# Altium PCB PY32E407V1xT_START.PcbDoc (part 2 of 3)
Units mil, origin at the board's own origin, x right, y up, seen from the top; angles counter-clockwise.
Board outline 1968.43 x 4717 mil, 2 copper layers (Top Layer, Bottom Layer), stack 21 mil thick; 210 components, 217 nets, 824 pads, 371 vias.
Unrouted connection lines stored in the file: 1.
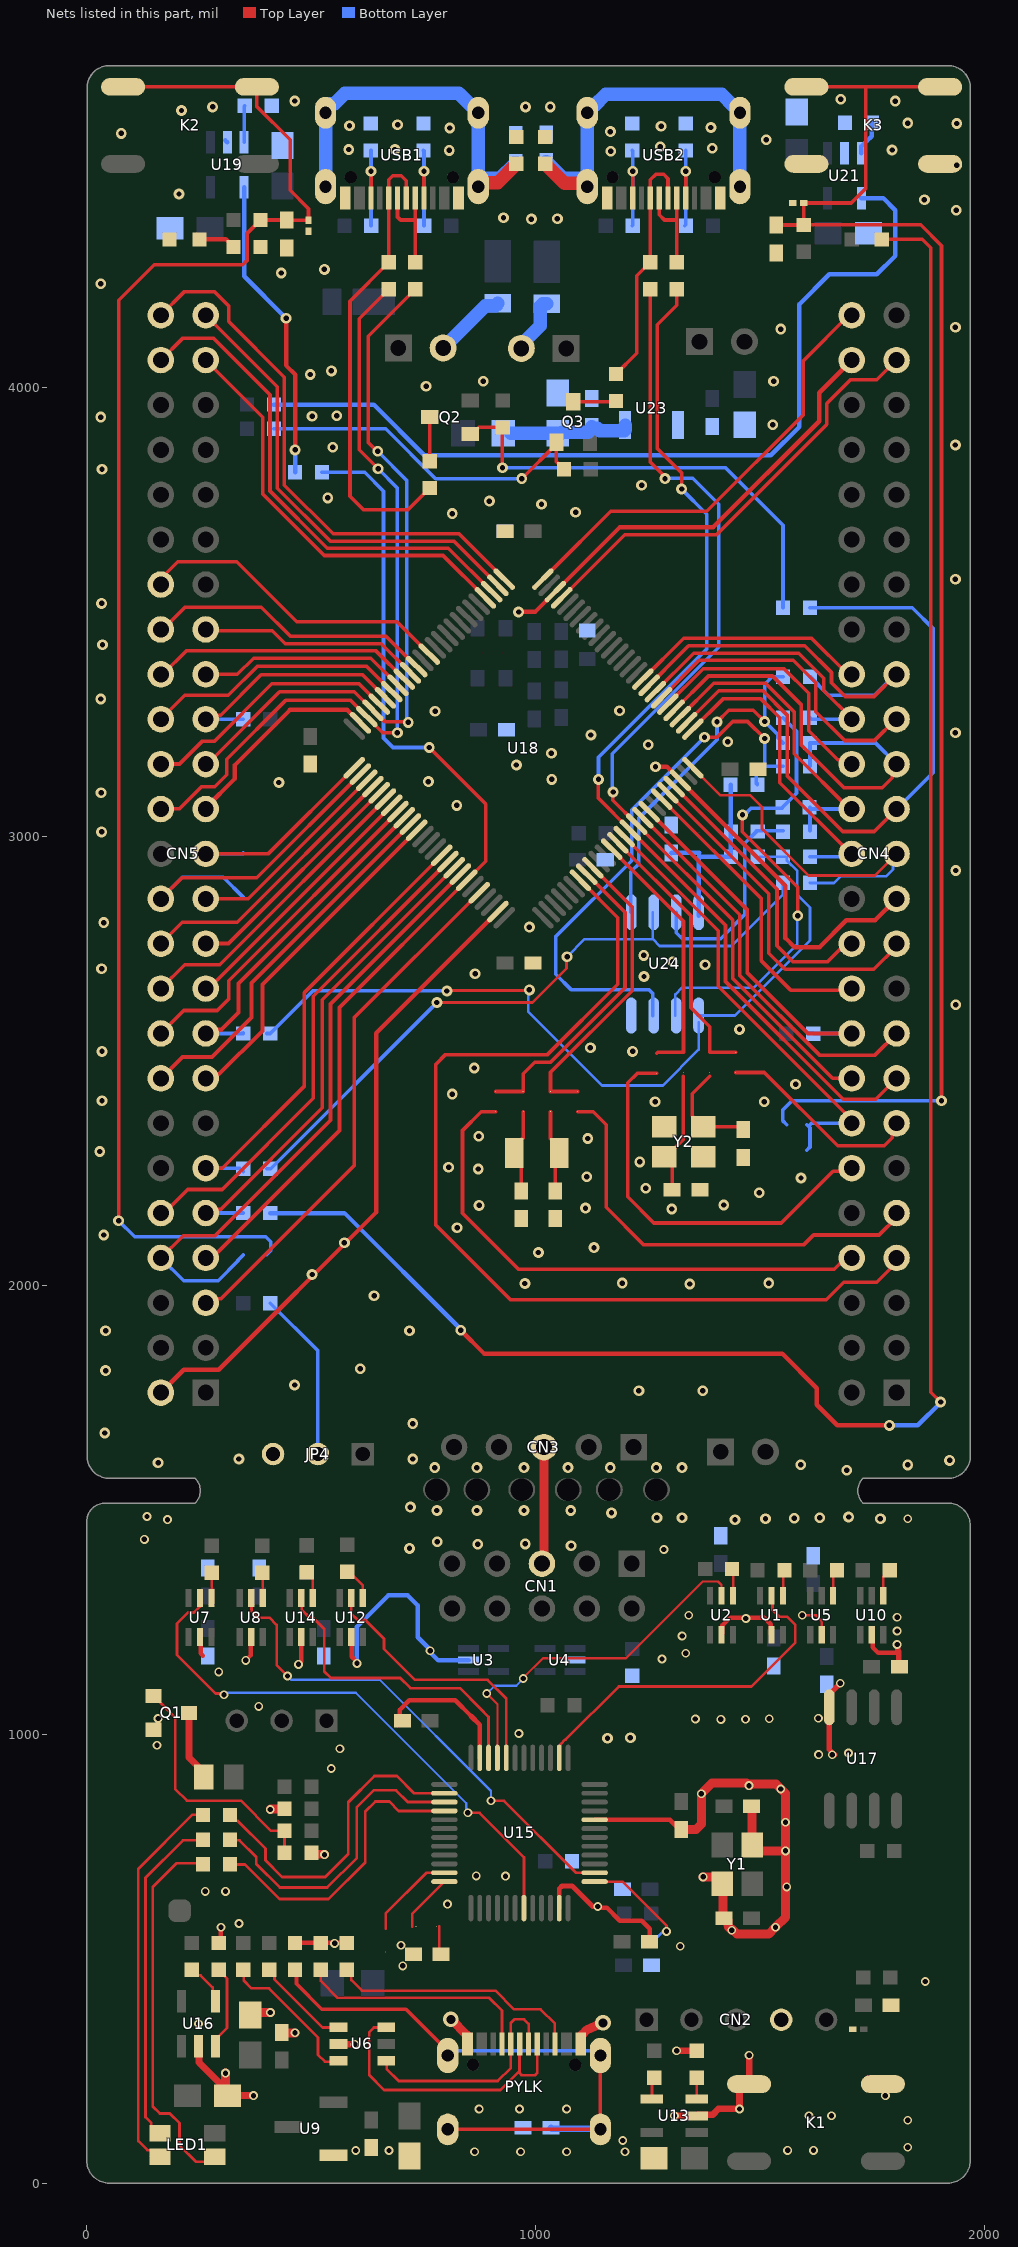
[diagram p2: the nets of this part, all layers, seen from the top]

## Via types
v1: diameter 24, hole 12, Top Layer to Bottom Layer, tented both sides, 208 vias
v2: diameter 19.68, hole 11.81, Top Layer to Bottom Layer, tented both sides, 106 vias
v3: diameter 19.68, hole 11.81, Top Layer to Bottom Layer, 37 vias
v4: diameter 35, hole 20, Top Layer to Bottom Layer, tented both sides, 16 vias
v5: diameter 30, hole 15, Top Layer to Bottom Layer, tented both sides, 2 vias
v6: diameter 40, hole 20, Top Layer to Bottom Layer, tented both sides, 2 vias

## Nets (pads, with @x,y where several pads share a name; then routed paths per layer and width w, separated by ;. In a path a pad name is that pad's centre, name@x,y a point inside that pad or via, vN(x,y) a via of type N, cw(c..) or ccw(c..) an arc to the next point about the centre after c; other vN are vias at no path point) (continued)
DIR_TCK_SWCLK: U2.5 U15.21 | length 808
  Top Layer w5: v2(891.12,1090.67) 914.79,1067 U15.21@914.79,947.32 ; v3(972.49,1124.13) 972.49,1125.57 1016.33,1169.41 1201.34,1169.41 1315.71,1283.79 1372.38,1340.46 1406.19,1340.46 1414.21,1332.43 U2.5@1414.21,1308.31
  Bottom Layer w5: v2(891.12,1090.67) 908.61,1108.16 956.52,1108.16 v3(972.49,1124.13)
DIR_TDI_VCP_TX: U12.5 U15.20 | length 603.7
  Top Layer w6: U12.5@589.12,1303.31 589.12,1268.77 602.92,1254.98 619.97,1254.98 662.25,1212.7 662.25,1189.92 731.11,1121.06 892.64,1121.06 934.47,1079.24 U15.20@934.47,947.32
DIR_TDO_SWO: U7.5 U15.43 | length 1242.4
  Top Layer w6: U7.5@252.55,1303.31 252.55,1284.73 238.94,1271.13 225.97,1271.13 201.14,1246.3 201.14,1176.38 286.99,1090.52 302.93,1090.52 v3(305.55,1087.9) ; v2(849,825) 874.69,825 973.84,725.85 U15.43@973.84,612.68
  Bottom Layer w5: v3(305.55,1087.9) 310.05,1092.41 599.21,1092.41 845.36,846.25 845.36,828.64 v2(849,825)
DIR_TMS_SWDIO: U1.5 U15.14 | length 784.3
  Top Layer w6: U15.14@1052.58,947.32 1052.58,973.99 1055.95,977.36 1055.95,978.29 1065.51,987.85 1066.44,987.85 1185.13,1106.54 1480.8,1106.54 1578.4,1204.13 1578.4,1243.36 1559.78,1261.98 1542.79,1261.98 1527.52,1277.25 1527.52,1306.42 U1.5@1525.64,1308.31
DIR_TRST_RTS: U8.5 U15.2 | length 1100.7
  Top Layer w6: U8.5@366.26,1303.31 366.85,1302.72 366.85,1274.24 381.53,1259.56 407.14,1259.56 422.94,1243.76 422.94,1153.79 v2(447.06,1129.67) ; v2(900.52,851.68) 929.72,851.68 1089.98,691.42 U15.2@1131.32,691.42
  Bottom Layer w5: v2(447.06,1129.67) 455.33,1121.41 652.59,1121.41 900.52,873.48 v2(900.52,851.68)
DIR_VCP_RX: U14.5 U15.22 | length 688.5
  Top Layer w6: U14.5@477.69,1303.31 479.07,1301.93 479.07,1277.14 495.6,1260.6 503.2,1260.6 529,1234.81 529,1140.06 543.61,1125.45 698.3,1125.45 721.05,1102.71 831.18,1102.71 875.38,1058.51 895.1,1038.79 U15.22@895.1,947.32
ESMC_CLK: R69.1 R70.1 U24.6 | length 1516.3
  Top Layer w6: v1(780,2630) 993.08,2630 1068.77,2705.69 1068.77,2730.51 v1(1070,2731.74)
  Bottom Layer w6: v1(1070,2731.74) 1109.26,2771 1261,2771 ; U24.6@1261,2831 1261,2771 ; R69.1@1551.01,2897 1551.01,2871.01 1436,2756 1276,2756 1261,2771
  Bottom Layer w8: R70.1@400.75,2260 410,2260 v1(780,2630)
ESMC_CS: R62.1 R67.1 R68.1 U24.1 | length 1810
  Top Layer w6: v1(802.28,2655.72) 803.42,2656.86 984.86,2656.86 v1(986,2658)
  Bottom Layer w6: v1(986,2658) 983.13,2655.13 983.13,2610.3 1148.11,2445.32 1283.32,2445.32 1363,2525 1363,2585.54 U24.1@1363,2583.32 ; U24.1@1361,2601 1443.8,2601 1611,2768.2 1611,2841.6 1583,2869.6 1583,2923.01 1559.26,2946.75 1559.26,2955 R62.1@1495,2954.99
  Bottom Layer w8: R67.1@400.75,2561 R67.1@409,2561 503.72,2655.72 v1(802.28,2655.72)
ESMC_IO0: R71.1 R74.1 U24.5 | length 826.7
  Top Layer w8: v1(1404,3255) 1430,3281 1485,3281 v1(1510,3256)
  Bottom Layer w8: U24.5@1212,2831 1212,2921.37 1230,2939.37 1230,3041.06 1404,3215.06 v1(1404,3255) ; R74.1@1551.01,3208 1539.01,3220 1539.01,3226.99 v1(1510,3256) 1510,3339 1527,3356 R71.1@1551.01,3356
ESMC_IO1: R72.1 R73.1 U24.2 | length 1023.9
  Top Layer w8: v1(1460.82,3047.82) 1460.43,3047.43 1460.43,3010.57 1584,2887 v1(1584,2823)
  Bottom Layer w6: U24.2@1311,2601 1311,2648 1326,2663 1486,2663 1583,2760 1583,2822 v1(1584,2823)
  Bottom Layer w8: v1(1460.82,3047.82) 1465.15,3047.82 1480.43,3063.1 R72.1@1549.11,3063.1 ; R72.1@1550,3065 1581,3096 1581,3234.01 R73.1@1551.01,3264
ESMC_IO2: R75.1 R76.1 U24.3 | length 1279.4
  Top Layer w8: v1(1376,3221) 1404,3221 1439,3256 1472,3256 v1(1510,3218)
  Bottom Layer w8: U24.3@1261,2601 1261,2650 1253,2658 1080,2658 1045,2693 1045,2777 1214,2946 1214,3059 v1(1376,3221) ; R76.1@1494,3118 R76.1@1494,3115 1491,3118 1491,3139 1491,3156 1510,3156 ; v1(1510,3218) 1510,3156 ; R75.1@1551.01,3156 1510,3156
ESMC_IO3: R77.1 R78.1 U24.7 | length 481.6
  Bottom Layer w8: U24.7@1313,2831 1313.47,2830.53 1313.47,2785.53 1327,2772 1412,2772 1466,2826 1466,2985 R78.1@1492,3011 ; R78.1@1491.38,3013 R77.1@1551.01,3013
F_VDD: C53.2 R50.2 R62.2 R76.2 R78.2 U24.8 | length 426.4
  Bottom Layer w10: C53.2@1302,2963 1303,2964 R50.2@1364,2964 ; U24.8@1363,2823 1363,2954.99 R62.2@1435,2954.99 R78.2@1435,3011 R76.2@1435,3115
GND: C1.1 C2.1 C3.1 C4.1 C5.1 C6.1 C7.1 C8.1 C9.1 C10.1 C11.1 C12.1 C13.1 C14.1 C15.1 C16.1 C17.1 C18.1 C19.1 C20.1 C21.1 C22.1 C23.1 C24.1 C25.1 C26.1 C27.1 C28.2 C29.1 C30.1 C31.1 C32.1 C33.1 C34.1 C35.1 C36.1 C37.1 C38.1 C39.1 C40.1 C41.1 C46.1 C47.1 C48.1 C49.1 C50.1 C51.1 C52.1 C53.1 CN1.5 CN2.4 CN3.3 CN4.23 CN4.48 CN5.2 CN5.27 CN5.38 JP4.3 K1.3 K1.4 K3.3 K3.4 L1.2 LED3_VDD*.2 PYLK.A1 PYLK.A12 PYLK.B1 PYLK.B12 Q1.2 R1.1 R3.2 R7.2 R19.1 R20.1 R24.1 R27.2 R29.1 R32.2 R49.1 R54.1 R56.2 R57.1 R61.2 R80.1 R82.1 R83.2 R84.1 R86.2 U1.2 U2.2 U3.2 U4.2 U5.2 U6.2 U7.2 U8.2 U9.1 U10.2 U11.2 U12.2 U13.2 U14.2 U15.8 U15.23 U15.47 U16.2 U17.4 U18.23 U18.48 U18.63 U18.74 U18.99 U19.2 U20.2 U21.2 U22.2 U23.1 U24.4 USB1.A1 USB1.A12 USB1.B1 USB1.B12 USB2.A1 USB2.A12 USB2.B1 USB2.B12 Y1.2 Y1.4 Y2.2 Y2.4 | length 8964.6
  Top Layer w6: v2(1594,1265) 1624,1265 1637.06,1251.94 U5.2@1637.06,1221.69
  Top Layer w8: CN5.38@165,3561 165,3574 202.49,3611.49 334.43,3611.49 468.09,3477.83 691.17,3477.83 U18.63@762.82,3406.18
  Top Layer w10: CN5.2@165,1761 215.84,1811.84 294.03,1811.84 644.48,2162.29 644.48,2561.77 896.41,2813.7 U18.99@915.41,2832.67 ; U7.2@252.55,1216.69 253.54,1215.7 253.54,1180.08 258.36,1175.25 ; CN5.27@265,3061 265,3063.91 330.04,3128.96 330.04,3159.04 452.68,3281.68 580.6,3281.68 609.21,3253.06 U18.74@609.7,3253.06 ; R29.1@294,535 299,540 v2(299,570) ; C15.1@309,210 309,200 C15.1@314,195 ; v2(354,1164.6) 364.89,1175.49 364.89,1215.32 U8.2@366.26,1216.69 ; C1.1@364,375 C1.1@369,380 ; C2.1@434,336 C2.1@435,335 ; R7.2@464,535 v2@552.95,535 ; v2(471.9,1155.7) 477.59,1161.39 U14.2@477.59,1216.59 ; R19.1@500.52,735.88 R19.1@502.04,737.4 ; v2(552.1,534.15) v2@552.95,535 ; R3.2@579,535 v2@552.95,535 ; U12.2@589.12,1216.69 590.41,1215.4 590.41,1172.62 600.83,1162.2 600.83,1156.83 v2@599,1155 ; C20.1@692.36,1020 702.36,1030 C20.1@703,1030 696.95,1036.05 696.95,1054.14 718.23,1075.42 820.98,1075.42 855.82,1040.58 ; C16.1@727.59,509.5 C16.1@728.59,510.5 ; PYLK.A1@842.31,309.89 PYLK.B12@854.12,309.89 ; v1(962,3500) 998.61,3500 U18.48@1043.99,3545.37 1187.66,3689.04 1395.79,3689.04 1631.48,3924.73 1631.48,3988.48 CN4.48@1704,4061 ; PYLK.B1@1094.28,309.89 PYLK.A12@1106.09,309.89 ; v2@1138.47,613.56 v2@1138.6,613.69 ; v2@1140.61,614.02 1158.36,614.02 1187.57,584.8 1236.07,584.8 1253.91,566.95 C19.1@1253.87,537.59 ; v1(1267,3155) 1292.39,3155 U18.23@1322.37,3125.01 ; U18.23@1322.84,3124.06 1341.38,3105.52 1341.38,3105.06 1556.39,2890.04 1556.39,2773.49 1576.45,2753.43 1632.43,2753.43 1692,2813 1756,2813 CN4.23@1804,2861 ; U2.2@1413.26,1220.75 U2.2@1414.21,1221.69 1416.1,1223.58 1416.1,1242.95 1433.15,1260 v2@1469.02,1260 ; v2(1468.2,1257.6) 1469.02,1258.42 v2@1469.02,1260 ; U1.2@1525.64,1221.69 1523.75,1223.58 1523.75,1245.25 1509,1260 v2@1469.02,1260 ; U10.2@1748.49,1221.69 1750.38,1219.8 1750.38,1193.96 1762.61,1181.72 1809.04,1181.72
  Top Layer w11: 855.82,1040.58 875.42,1020.98 U15.23@875.42,947.32 ; U15.47@1052.58,612.68 1052.58,655.91 1058.74,662.07 1081.08,662.07 1126.87,616.28 v2(1138.35,616.28) ; U15.8@1131.32,809.53 1298.94,809.53 1320.47,788 C21.1@1324.12,788
  Top Layer w12: Q1.2@149.2,1009.8 Q1.2@154.01,1004.99 ; v2(1660.71,954.27) 1665.84,954.27 1654,966.11 U17.4@1654,1060 1654,1088.88 1678.39,1113.27 v2(1678.39,1113.51) ; v2(1805.2,1200) 1806.67,1198.53 1806.67,1186.53 1809.04,1184.16 1809.04,1181.72 1809.04,1150.96 C17.1@1810,1150 ; v2@1867.5,449.5 v2(1868,449)
  Top Layer w15: U16.2@248.48,304.48 249.91,303.04 249.91,269.09 C15.1@309,210 ; C15.1@314,195 v2(371.56,195) ; U6.2@569.66,310.05 571.24,308.47 572.29,309.52 v2(597.08,309.52) ; v2(1309,150) U13.2@1359,150 1361.16,152.16 1393.66,152.16 1407.23,165.74 v2@1453.26,165.74 ; v2(1314,295) R24.1@1359,295 ; v2(1454,165) 1454,209.44 1465.26,220.7 K1.4@1475.55,220.7 v2(1475.55,285) ; K1.3@1739.36,231.96 1750.61,220.7 K1.3@1773.55,220.7
  Top Layer w20: C15.1@309,210 v2(309,245) ; C1.1@369,380 v2(409,380) ; v2(408.83,832.29) 409.59,833.04 440.17,833.04 R20.1@440.93,833.8 ; C2.1@435,335 v2(464,335) ; R19.1@502.04,737.4 502.04,737.12 506.52,732.64 528.94,732.64 v2(529.7,731.87) ; v4@811.73,365 PYLK.A1@846.74,329.99 ; CN1.5@1014,1380 1018.26,1384.26 CN3.3@1018.26,1639.56 ; PYLK.A12@1103.44,330.9 1114.26,341.72 v4(1150,357) ; C21.1@1319.12,797 1324.12,792 C21.1@1324.12,788 1324.41,788.28 1357.41,788.28 1369.12,800 v2(1369.12,867.57) 1392.95,891.41 1469.41,891.41 v2(1475.26,885.55) 1476.35,885.55 1479.45,888.65 1535.47,888.65 v2(1546.03,878.1) 1556.58,867.54 v2(1556.58,803.85) 1556.58,740.13 1556.58,592.46 v2(1534.12,570) 1518.85,554.73 1448.89,554.73 v2@1438.64,564.98 ; v2(1372.98,682.29) 1400.06,682.29 Y1.2@1415.66,666.69 1417.39,664.96 1417.39,591.73 C18.1@1419.12,590 1423.12,590 1428.12,585 1428.12,575.5 1429.37,574.25 ; 1429.37,570.63 v2(1436.83,563.18) ; C24.1@1481.12,840 1481.85,839.27 1481.85,754.04 Y1.4@1482.59,753.31 1495.74,740.16 v2(1556.55,740.16)
  Bottom Layer w6: v2@598.26,1157.83 v2(601.89,1157.83)
  Bottom Layer w10: U19.2@308,4551 U19.2@313,4546 ; v2(601.89,1157.83) 601.89,1239.49 671.46,1309.06 714.72,1309.06 737,1286.78 737,1215.79 764.89,1187.9 v2(764.89,1185.89) ; v2@764,1183 782.72,1164.28 849.81,1164.28 U3.2@850.54,1165
  Bottom Layer w20: CN1.5@1014,1380 CN1.5@1020,1386 ; CN3.3@1018.26,1639.56 CN3.3@1020,1637.82 ; CN3.3@1020,1639.56 CN3.3@1020,1642.94
  other v1: 1160,991 1211,992 719,1414 1079,1420 871,1423 977,1424 781,1429 1444,1478 1512,1480 1768,1480 1576,1481 1270,1482 1326,1482 1633,1482 1697,1484 1169,1493 780,1498.5 869,1498.5 974,1498.5 1078,1498.5 721,1506 1693,1588 775,1594 869,1594 974,1594 1072,1594 1166,1594 1269,1594 1326,1594 1590.7,1600.13 1829,1600 159,1605 1922,1610 339,1613 726,1613 40,1671 726,1692 1230,1765 1372,1765 463,1778 42,1810 609,1814 42,1899 719,1899 640,1977 1343,2003 976,2004 1193,2005 1519,2005 502,2024 1006,2073 1130,2084 574,2095 38,2112 825,2128 1303,2170 1111,2172 874,2178 1419,2179 1498,2206 1245,2216 1591,2239 1114,2242 872,2259 806,2263 1232,2275 29,2298 1116,2327 873,2332 1266,2409 1509,2409 34,2411 814,2426 1579,2448 863,2484 34,2521 1216,2521 1122,2529 1454,2570 1936,2625 1241.25,2687.96 865,2694 33,2705 1377.48,2713.98 1305.24,2721 1241,2735 986,2798 38,2808 1936,2924 33,3010 824,3069 32,3097 428,3120 761,3122 1036,3127 957,3159 1035,3185 1251,3204 1427.97,3211.03 1123,3226 1935,3231 776,3279 1187,3280 31,3306 35,3427 33,3519 1935,3573 814,3719 1089,3722 1013,3740 897,3747 537,3754 1236,3782 34,3818 548,3867 1935,3872 1528,3917 31,3934 502,3936 557,3937 756,4003 883,4014 1530,4014 498,4029 545,4037 1546,4130 1935,4134 31,4231 433.41,4255.1 529.41,4263.1 990.41,4375.1 1048.41,4376.1 928.41,4378.1 1937,4395 1866,4418 205.41,4431.1 1938,4495 1167.41,4526.1 807.41,4528.1 1794,4529 583.41,4530.1 686.41,4530.1 1393.41,4533.1 1277.41,4536.1 1513.41,4552.1 77,4566 1166.41,4570.1 808.41,4578.1 1390.41,4579.1 1279.41,4582.1 585.41,4583.1 692.41,4585.1 1938,4588 1829,4589 211,4617 280.41,4625.1 977.41,4625.1 1032.41,4625.1 463.41,4638.1 1801,4638 1679.41,4642.1
  other v2: 864,70 966.5,70 1069,70 1199,70 1561.25,73 1619,73 1829,80 1194,95 1829,140 1609,150 1659,150 874,165 964,165 1069,165 1779,195 249,355 264,650 309,650 1559.12,660 156.3,975.34 159,1035 1281.35,1167.57 1340.94,1264.95 180,1478 1829,1480 134,1485
  other v3: 599.23,72.73 673.48,72.72 704,484 1322.05,527.77 700,530 338.93,578.18 803.43,621.59 932.63,683.94 867.47,684.5 544.71,923.68 1630.33,954.53 1696.76,958.38 563.86,967.62 962.55,1001.58 1412.59,1033.06 1467.58,1033.45 1355.66,1033.84 1520.24,1034.63 1629.67,1035.55 383,1062 294,1139 1334.29,1180.47 1326.19,1218.9 1805.2,1229.78 1805.2,1260.65 1285.59,1411.54 128.3,1434.1
  other v4: 811.08,365
L_USB1_CN_DM: R63.2 USB1.A7 USB1.B7 | length 226.2
  Top Layer w8: USB1.A7@692.16,4421.92 692.16,4379.84 699,4373 731,4373 ; R63.2@732,4279 732,4373 USB1.B7@732,4421.45
L_USB1_CN_DP: R64.2 R93.1 USB1.A6 USB1.B6 | length 1036.3
  Top Layer w8: R64.2@672.47,4279.53 USB1.B6@672.47,4421.92 672.47,4462.47 681.53,4471.53 700.75,4471.53 711.84,4460.44 USB1.A6@711.84,4421.92 ; R64.2@673,4279 586.32,4192.32 586.32,3757.68 616,3728 716,3728 R93.1@764,3776
L_USB2_CN_DM: R87.2 USB2.A7 USB2.B7 | length 223.2
  Top Layer w8: USB2.A7@1275.16,4421.92 1275.16,4384.84 1287,4373 1314,4373 ; R87.2@1314.53,4279.53 USB2.B7@1314.53,4421.92
L_USB2_CN_DP: R88.2 R96.1 USB2.A6 USB2.B6 | length 555.4
  Top Layer w8: R96.1@1179,4030 1225,4076 1225,4249 R88.2@1255,4279 ; R88.2@1255.47,4279.47 USB2.B6@1255.47,4421.92 1255.47,4462.47 1268,4475 1285,4475 1294.84,4465.16 USB2.A6@1294.84,4421.92
L_USB_CN_DM: PYLK.A7 PYLK.B7 U6.4 | length 510.4
  Top Layer w6: U6.4@667.15,272.6 668.18,271.57 668.18,254.46 695.04,227.6 915.36,227.6 944.67,256.9 PYLK.B7@944.67,309.89 944.67,357.33 952.34,365 974,365 984.31,354.69 PYLK.A7@984.31,310.16
L_USB_CN_DP: PYLK.A6 PYLK.B6 U6.6 | length 673.6
  Top Layer w6: U6.6@667.15,347.4 666.26,346.51 639.39,346.51 629.35,336.47 629.35,240.4 662.22,207.53 921.27,207.53 961.55,247.81 963.95,250.21 ; 964.1,249.74 PYLK.A6@964.1,309.64 ; 964.75,244.61 964.75,247.81 ; 965.31,244.04 969.05,240.31 998.06,240.31 1003.3,245.55 1003.3,309.46 PYLK.B6@1003.73,309.89
LED_BLUE: R8.2 U15.28 | length 674.3
  Top Layer w6: R8.2@319,710 352.51,710 429.7,632.81 538.56,632.81 620.33,714.58 620.33,827.41 642.92,850 674,850 694.79,829.21 U15.28@796.68,829.21
LED_GREEN: R5.2 U15.26 | length 726.2
  Top Layer w6: R5.2@319,820 332,807 336.4,807 398.27,745.13 398.27,719.27 435.41,682.13 531.27,682.13 582.48,733.34 582.48,848.48 640.75,906.75 690.91,906.75 729.07,868.58 U15.26@796.68,868.58
LED_RED: R4.2 U15.27 | length 697.6
  Top Layer w6: R4.2@319,765 320.4,763.6 340.49,763.6 377.6,726.48 377.6,711.05 430.22,658.43 535.52,658.43 601.68,724.59 601.68,837.68 639,875 689,875 715.1,848.9 U15.27@796.68,848.9
NetC16_2: C16.2 R30.2 | length 64.1
  Top Layer w6: 785.21,571.75 785.21,513.88 C16.2@789.59,509.5
NetC25_2: C25.2 R36.1 Y2.3 | length 280
  Top Layer w8: C25.2@1304,2212.99 1304,2269.22 Y2.3@1286.69,2286.53 1290.63,2286.53 1329,2324.9 1329,2466
NetC27_2: C27.2 R40.1 Y2.1 | length 232.5
  Top Layer w8: 1388,2465.99 1348.97,2426.96 1348.97,2377.76 1349.75,2376.99 1349.75,2373.08 1369.37,2353.46 1455.53,2353.46 C27.2@1462,2346.99
NetC28_1: C28.1 R42.2 Y3.2 | length 191.5
  Top Layer w8: C28.1@968,2210.5 968,2278.81 Y3.2@951.81,2295 951.81,2307.8 971.97,2327.97 R42.2@971.97,2386.97
NetC29_2: C29.2 R43.2 Y3.1 | length 187.8
  Top Layer w8: R43.2@1032.97,2386.97 1032.97,2327.02 1052.2,2307.8 1044,2299.6 C29.2@1044,2210.5
NetC34_2: C34.2 K3.1 K3.2 R51.2 R52.1 U20.1 | length 3420.3
  Top Layer w8: C34.2@1536,4366 C34.2@1536,4362 R51.2@1597,4362 R51.2@1597.3,4362.3 ; K3.1@1603,4669.7 1734,4669.7 ; K3.2@1901,4669.7 1734,4669.7 ; v1(1904,2411) 1904,4316 1857.7,4362.3 R51.2@1597.3,4362.3 ; R51.2@1597.3,4362.3 U20.1@1597.3,4411 1703.15,4411 1735.68,4443.52 1735.68,4668.02 1734,4669.7
  Bottom Layer w8: R52.1@1559.26,2358 1550,2367.26 1550,2390 1571,2411 v1(1904,2411)
NetC35_2: C35.2 K2.3 K2.4 R53.1 R54.2 U22.1 | length 3617.4
  Top Layer w8: v1(70.9,2144) 71.25,2144.35 71.25,4194.07 150.59,4273.41 347.5,4273.41 357.04,4282.95 357.04,4343.04 R54.2@387,4373 ; K2.4@81,4669.7 K2.3@379,4669.7 379,4626 453,4552 453,4439.15 494,4398.15 U22.1@494,4372.3 446.7,4372.3 C35.2@446,4373 R54.2@387,4373 ; R54.2@386.7,4373.3 R54.2@387,4373
  Bottom Layer w8: v1(70.9,2144) 106.9,2108 399,2108 410,2097 410,2077.25 R53.1@400.75,2068
NetC38_2: C38.2 C39.2 F2.2 U23.3 | length 276.9
  Bottom Layer w30: F2.2@944,3898 C38.2@1049,3898 1056.23,3898 1059,3900.77 1116.77,3900.77 C39.2@1125,3909 ; C39.2@1125,3913 C39.2@1125,3909 ; U23.3@1199.29,3916.16 1199.29,3905.89 1197.52,3904.11 1142.57,3904.11 1137.69,3909 C39.2@1125,3909
NetC40_2: C40.2 PYLK.1 PYLK.2 PYLK.3 PYLK.4 R7.1 | length 1406.9
  Top Layer w8: R7.1@464,475 467.29,471.71 467.29,443.87 523.64,387.52 710.97,387.52 804.12,294.37 PYLK.1@804.12,284.29 ; PYLK.3@804.12,119.73 PYLK.4@1144.28,119.73 PYLK.2@1144.28,284.29
  Bottom Layer w8: PYLK.1@815.04,295.21 PYLK.2@1133.36,295.21
  Bottom Layer w15: C40.2@1034,123 1035.64,121.36 1142.64,121.36 PYLK.4@1144.28,119.73
  Bottom Layer w20: PYLK.1@804.12,284.29 PYLK.1@815.04,295.21 ; PYLK.2@1133.36,295.21 PYLK.2@1144.28,284.29
NetC48_2: C48.2 R61.1 USB1.1 USB1.2 USB1.3 USB1.4 | length 897.8
  Top Layer w30: USB1.1@872.08,4447.52 872.08,4448.27 880.04,4456.23 915.23,4456.23 R61.1@957,4498
  Bottom Layer w30: USB1.2@531.92,4447.52 531.92,4619.23 545.21,4632.52 552.36,4632.52 574.84,4655 829.16,4655 USB1.3@856.97,4627.19 ; USB1.1@872.08,4447.52 USB1.1@872.08,4458.6 ; USB1.3@872.08,4612.08 USB1.1@872.08,4458.6 ; C48.2@956,4501 956,4497 952,4497 921.56,4466.56 880.04,4466.56 USB1.1@872.08,4458.6
NetC52_2: C52.2 R86.1 USB2.1 USB2.2 USB2.3 USB2.4 | length 912.5
  Top Layer w30: R86.1@1021,4498 1064.43,4454.57 1107.87,4454.57 USB2.2@1114.92,4447.52
  Bottom Layer w30: C52.2@1024,4503 1024,4499 1028,4499 1060.44,4466.56 1106.96,4466.56 USB2.2@1114.92,4458.6 ; USB2.2@1114.92,4447.52 USB2.2@1114.92,4458.6 ; USB2.3@1439.97,4627.19 1414.16,4653 1155.84,4653 1130.03,4627.19 1122.89,4627.19 1114.92,4619.23 USB2.4@1114.92,4612.08 USB2.2@1114.92,4458.6 ; USB2.1@1455.08,4447.52 USB2.3@1455.08,4612.08
NetD2_2: D2.2 JP5.2 | length 163.1
  Bottom Layer w30: JP5.2@794,4088 887.58,4181.58 910.33,4181.58 D2.2@916,4187.25
NetD3_2: D3.2 JP6.2 | length 128
  Bottom Layer w30: JP6.2@968,4087 968,4095.12 1010.47,4137.59 1010.47,4180.58 1016.14,4186.25 D3.2@1025,4186.25
NetJP4_2: JP4.2 R41.1 | length 379.8
  Bottom Layer w8: R41.1@409,1960 515,1854 JP4.2@515,1624.13
NetLED1_2: LED1.2 R8.1 | length 846.1
  Top Layer w6: R8.1@259,710 256.67,712.33 199.33,712.33 147,660 147,171 162.8,155.2 184.86,155.2 206.53,133.53 206.53,84.16 242.82,47.87 274.08,47.87 LED1.2@285.02,58.82
NetLED1_3: LED1.3 R5.1 | length 884.3
  Top Layer w6: LED1.3@143.28,58.52 LED1.3@157.98,43.82 ; LED1.3@162.98,58.82 148.28,73.52 135.09,73.52 115,93.61 115,700.34 235.59,820.93 258.07,820.93 R5.1@259,820
NetLED1_4: LED1.4 R4.1 | length 755.1
  Top Layer w6: LED1.4@155.66,98.5 143.36,110.81 143.36,134.74 131,147.09 131,680.34 214.39,763.73 257.73,763.73 R4.1@259,765
NetLED2_PB5_2: LED2_PB5.2 R46.1 | length 4430.9
  Top Layer w8: LED2_PB5.2@1771,4330 1861,4330 1880,4311 1880,1762 v1(1902,1740)
  Top Layer w10: v1(833,1900) 885,1848 1549,1848 1626,1771 1626,1734 1672,1688 v1(1788,1688)
  Bottom Layer w10: R46.1@409,2161 574,2161 833,1902 v1(833,1900) ; v1(1788,1688) 1851,1688 1902,1739 v1(1902,1740)
NetLED3_VDD*_1: LED3_VDD*.1 R59.1 | length 83
  Top Layer w10: LED3_VDD*.1@251,4330 310,4330 R59.1@327,4313
NetPYLK_A5: PYLK.A5 R1.2 | length 530.3
  Top Layer w6: R1.2@521.49,474.99 521.49,449.82 558.51,412.79 896.58,412.79 924.99,384.38 PYLK.A5@924.99,309.89
NetPYLK_B5: PYLK.B5 R3.1 | length 566
  Top Layer w6: R3.1@579,475 589.31,464.69 589.31,452.34 612.85,428.8 910.11,428.8 951.66,387.24 1010.55,387.24 1042.6,355.19 1042.6,310.4 PYLK.B5@1043.1,309.89
NetQ1_1: Q1.1 R18.1 R19.2 | length 559
  Top Layer w6: Q1.1@149,1084.8 150.97,1084.8 162.72,1073.06 162.72,1071.23 197.46,1036.49 197.46,877.34 222.86,851.94 343.45,851.94 410.61,784.78 R18.1@440.53,784.78 ; R19.2@440.52,735.88 R18.1@440.52,784.77
NetQ1_3: Q1.3 R14.1 | length 166.5
  Top Layer w6: Q1.3@224.49,1044.15 Q1.3@227.74,1047.4 ; R14.1@260.54,905 R14.1@260.54,910.91
  Top Layer w15: Q1.3@227.74,1047.4 227.74,948.28 260.54,915.49 R14.1@260.54,905
NetQ2_1: Q2.1 R94.1 R95.2 | length 1030.9
  Top Layer w8: Q2.1@854.55,3896.6 858.49,3896.6 872.89,3911 924,3911 R95.2@927,3911 926,3910 v1(926,3821)
  Bottom Layer w8: v1(926,3821) 1423,3821 1551.01,3692.99 R94.1@1551.01,3509
NetQ2_3: Q2.3 R93.2 | length 98
  Top Layer w8: R93.2@764,3836 Q2.3@764,3934
NetQ3_1: Q3.1 R97.1 R98.2 | length 775.5
  Top Layer w8: v1(969,3797) 969.13,3797 Q3.1@1046.2,3874.06 ; Q3.1@1045.2,3879 Q3.1@1046.2,3878 Q3.1@1046.2,3874.06 ; R98.2@1063,3818 1046.2,3834.8 Q3.1@1046.2,3874.06
  Bottom Layer w8: R97.1@417,3908 666,3908 777,3797 v1(969,3797)
NetQ3_3: Q3.3 R96.2 | length 96
  Top Layer w8: Q3.3@1083.6,3968.55 1177.55,3968.55 R96.2@1179,3970
NetR2_1: R2.1 U1.4 | length 57.9
  Top Layer w6: U1.4@1551.23,1308.31 1551.23,1362.02 R2.1@1554.21,1365
NetR6_1: R6.1 U2.4 | length 57.8
  Top Layer w6: R6.1@1437.06,1365 1439.8,1362.27 U2.4@1439.8,1308.31
NetR9_1: R9.1 U5.4 | length 60.3
  Top Layer w6: U5.4@1662.66,1308.31 1662.66,1356.3 R9.1@1671.35,1365
NetR10_1: R10.1 U6.3 | length 332.9
  Top Layer w6: R10.1@349,475 349.77,474.23 349.77,451.69 367.41,434.05 405.8,434.05 515.24,324.61 515.24,285.87 530.63,270.48 558.74,270.48 U6.3@560.53,272.28
NetR11_1: R11.1 U6.1 | length 227.7
  Top Layer w6: R11.1@407.75,480 418.15,469.6 418.15,453.68 525,346.83 U6.1@570.97,346.83
NetR12_1: R12.1 U7.4 | length 59
  Top Layer w6: R12.1@272.55,1360 278.14,1354.41 U7.4@278.14,1303.31
NetR13_1: R13.1 U8.4 | length 60.8
  Top Layer w6: R13.1@379.94,1360.02 R13.1@389.82,1350.14 ; U8.4@391.86,1303.31 R13.1@391.86,1350.12
NetR17_1: R17.1 U10.4 | length 62.7
  Top Layer w6: U10.4@1774.08,1308.31 1774.08,1350.59 R17.1@1788.49,1365
NetR21_1: R21.1 U12.4 | length 75.3
  Top Layer w6: R21.1@580.63,1362.11 584.62,1362.11 614.71,1332.03 U12.4@614.71,1303.31
NetR23_2: R23.2 U13.4 | length 49.6
  Top Layer w6: U13.4@1259,187.5 1259,230 R23.2@1264,235
NetR24_2: R24.2 U13.3 | length 47.5
  Top Layer w6: U13.3@1359,187.5 R24.2@1359,235
NetR25_1: R25.1 U14.4 | length 62.8
  Top Layer w6: R25.1@490.2,1360.7 503.28,1347.62 U14.4@503.28,1303.31
NetR26_2: R26.2 U15.1 | length 256.3
  Top Layer w6: U15.1@1131.32,671.73 1193.18,671.73 1291.46,573.45 v3(1291.46,560.88)
  Bottom Layer w6: 1257.34,539.83 1262.61,539.83 1283.66,560.88 v3(1291.46,560.88)
NetR28_2: R28.2 U16.4 | length 96.1
  Top Layer w6: R28.2@234,475 246,463 253.44,463 280.5,435.94 280.5,411 U16.4@286.5,405
NetR29_2: R29.2 U16.3 | length 188.5
  Top Layer w6: U16.3@286.5,305 286.5,320 312.56,346.06 312.56,455.68 306,462.24 306,463 R29.2@294,475
NetR30_1: R30.1 U15.36 | length 129.6
  Top Layer w6: 725.21,571.75 725.21,600.26 U15.36@796.68,671.73
NetR32_1: R32.1 U15.35 | length 201.4
  Top Layer w6: 665.96,567.4 665.96,600.38 757,691.42 U15.35@796.68,691.42
NetR47_1: R47.1 R56.1 USB1.B5 | length 228.4
  Top Layer w8: USB1.B5@633.1,4421.92 v1(633.1,4481.9)
  Bottom Layer w8: R56.1@633,4528.01 633.1,4527.91 v1(633.1,4481.9) 633.1,4360.89 R47.1@634,4359.99
NetR48_1: R48.1 R49.2 USB1.A5 | length 228.5
  Top Layer w8: USB1.A5@751.21,4421.92 v1(751.21,4481.58)
  Bottom Layer w8: R49.2@750,4528 751.21,4526.79 v1(751.21,4481.58) 751.21,4360.79 R48.1@752,4360
NetR55_2: R55.2 U19.4 | length 682.1
  Top Layer w10: v1(444,4154) 444,4049 464.11,4028.89 v1(464.11,3861)
  Bottom Layer w10: U19.4@350.5,4446 350.5,4247.5 v1(444,4154) ; R55.2@464,3811 464.11,3811.11 v1(464.11,3861)
NetR57_2: R57.2 U19.3 | length 82.6
  Bottom Layer w8: U19.3@350.5,4546 350.5,4626.5 R57.2@352,4628
NetR65_1: R65.1 R83.1 USB2.B5 | length 228.9
  Top Layer w8: USB2.B5@1216.1,4421.92 v1(1216.1,4481.9)
  Bottom Layer w8: R65.1@1215,4359.99 1216.1,4361.09 v1(1216.1,4481.9) 1216.1,4526.91 R83.1@1215,4528.01
NetR66_1: R66.1 R80.2 USB2.A5 | length 228.7
  Top Layer w8: USB2.A5@1334.21,4421.92 v1(1334.21,4481.58)
  Bottom Layer w8: R66.1@1332,4360 1334.21,4362.21 v1(1334.21,4481.58) 1334.21,4527.79 R80.2@1334,4528
NetR81_2: R81.2 U21.4 | length 1963.3
  Bottom Layer w10: R81.2@417,3962 639,3962 752,3849 1524,3849 1587,3912 1587,4185 1654,4252 1760,4252 1801,4293 1801,4395 1774,4422 U21.4@1725.5,4422
NetR84_2: R84.2 U21.3 | length 78
  Bottom Layer w10: U21.3@1725.5,4522 1725.5,4537 1736.5,4548 1737,4548 1749,4560 R84.2@1749,4590
NRST: CN4.14 R39.2 R52.2 U18.14 | length 1000.3
  Top Layer w8: U18.14@1200.95,2995.89 1406.87,2789.97 1406.87,2666.27 1704,2369.14 CN4.14@1704,2361
  Bottom Layer w8: R39.2@1604.04,2301.03 1611,2307.99 1611,2351.06 R52.2@1604.04,2358.03 ; 1611.01,2358 1614.01,2361 CN4.14@1704,2361
OSC_32IN: CN4.8 R89.2 | length 1204.8
  Top Layer w8: R89.2@910.97,2386.97 878.88,2386.97 836.91,2345 836.91,2160.82 961.78,2035.94 1665.13,2035.94 1690.18,2061 CN4.8@1704,2061
OSC_32INa: R42.1 R89.1 U18.8 | length 695.3
  Top Layer w8: R89.1@911,2431.75 R42.1@972,2431.75 972,2471 998,2497 1032.94,2497 1199,2663.06 1199,2830.8 U18.8@1113.58,2916.22
OSC_32OUT: CN4.9 R90.2 | length 975.6
  Top Layer w8: R90.2@1093.97,2386.97 1128.03,2386.97 1157,2358 1157,2173.75 1239.98,2090.76 1597.76,2090.76 1619,2112 1764.92,2112 1804,2151.08 CN4.9@1804,2161
OSC_32OUTa: R43.1 R90.1 U18.9 | length 671
  Top Layer w8: R90.1@1094,2431.75 R43.1@1033,2431.75 1033,2474.43 1215,2656.43 1215,2842.64 U18.9@1127.5,2930.14
OSC_IN: CN4.12 R91.2 | length 912.8
  Top Layer w8: R91.2@1269.97,2471.97 1225.97,2471.97 1205,2451 1205,2197 1263.24,2138.76 1547,2138.76 1662.47,2254.24 1697.24,2254.24 CN4.12@1704,2261 CN4.12@1692.6,2261
OSC_INa: R36.2 R91.1 U18.12 | length 579.3
  Top Layer w8: U18.12@1169.26,2971.9 1169.26,2970.87 1189.27,2950.87 1189.27,2950.72 1329.25,2810.73 1329.25,2519.03 R36.2@1329.03,2519.03 1272.28,2519.03 R91.1@1270,2516.75
OSC_OUT: CN4.13 R92.2 | length 459.9
  Top Layer w8: R92.2@1445.97,2473.97 1509.34,2473.97 1672.75,2310.56 1776.18,2310.56 1794.23,2328.6 1794.23,2351.23 CN4.13@1804,2361
OSC_OUTa: R40.2 R92.1 U18.13 | length 609.7
  Top Layer w8: U18.13@1183.18,2985.82 1346.03,2822.97 1346.03,2618.02 1388.03,2576.02 R40.2@1388.03,2519.02 1445.73,2519.02 R92.1@1446,2518.75
PA0: CN4.20 U18.20 | length 676.7
  Top Layer w8: U18.20@1284.26,3079.41 1502.87,2860.8 1502.87,2722.64 1567.79,2657.72 1700.72,2657.72 CN4.20@1704,2661
PA1: CN4.21 U18.21 | length 777.3
  Top Layer w8: U18.21@1294.54,3097.17 1519.39,2872.32 1519.39,2740.02 1555.51,2703.9 1753.34,2703.9 1804,2754.57 CN4.21@1804,2761
PA2: CN4.22 U18.22 | length 647.1
  Top Layer w8: U18.22@1308.46,3111.1 1537.61,2881.95 1537.61,2756.52 1572.98,2721.15 1650.33,2721.15 1690.18,2761 CN4.22@1704,2761
PA3: CN4.25 R69.2 U18.25 | length 836.9
  Top Layer w6: U18.25@1350.21,3152.85 1411.07,3092 1477,3092 1504,3065 1504,3017 1608,2913 1756,2913 CN4.25@1804,2961
  Bottom Layer w6: R69.2@1611.01,2897 1611.77,2896.24 1664.64,2896.24 1679.4,2911 1780.75,2911 1796.13,2926.38 1796.13,2953.13 CN4.25@1804,2961
PA4: CN4.26 R68.2 U18.26 | length 704.6
  Top Layer w8: U18.26@1350.21,3239.15 1417.27,3306.21 1501.79,3306.21 1544,3264 1544,3119.67 1702.67,2961 CN4.26@1704,2961
  Bottom Layer w8: R68.2@1611.01,2955 1698,2955 CN4.26@1704,2961
PA5: CN4.27 R94.2 U18.27 | length 1456.5
  Top Layer w8: U18.27@1336.3,3253.06 1407.64,3324.41 1506.22,3324.41 1560,3270.63 1560,3135.19 1684.19,3011 1754,3011 CN4.27@1804,3061
  Bottom Layer w8: R94.2@1611.01,3509 1839,3509 1886,3462 1886,3143 CN4.27@1804,3061
PA6: CN4.28 R72.2 R77.2 U18.28 | length 729.7
  Top Layer w8: U18.28@1322.37,3266.99 1396.72,3341.29 1511.97,3341.29 1576,3277.25 1576,3184.1 1699.1,3061 CN4.28@1704,3061
  Bottom Layer w8: R77.2@1611.01,3013 1611.01,3065 1615.01,3061 CN4.28@1704,3061
PA7: CN4.29 R74.2 R75.2 U18.29 | length 981.2
  Top Layer w8: U18.29@1308.46,3280.9 1384.83,3357.29 1527.43,3357.29 1592,3292.72 1592,3203 1686.62,3108.38 1772.05,3108.38 1794.23,3130.55 1794.23,3151.23 CN4.29@1804,3161
  Bottom Layer w8: R75.2@1611.01,3156 R74.2@1611.01,3208 1757,3208 CN4.29@1804,3161
PA8: CN5.32 U18.69 | length 586.9
  Top Layer w8: CN5.32@165,3261 218.13,3314.13 315.54,3314.13 380.86,3379.45 622.51,3379.45 U18.69@679.3,3322.66
PA9: CN5.31 R60.1 U18.70 | length 546.4
  Top Layer w8: CN5.31@265,3261 274.09,3270.09 298.64,3270.09 388.33,3359.77 614.35,3359.77 U18.70@665.38,3308.74
  Bottom Layer w8: CN5.31@265,3261 R60.1@349,3261
PA10: CN5.30 U18.71 | length 579.1
  Top Layer w8: CN5.30@165,3161 165.26,3161.26 206.53,3161.26 256.79,3211.51 284.07,3211.51 412.3,3339.74 606.55,3339.74 U18.71@651.46,3294.83
PA11: CN5.29 R63.1 U18.72 | length 1592.4
  Top Layer w8: CN5.29@265,3161 268.24,3161 429.56,3322.32 596.12,3322.32 U18.72@637.54,3280.9 638.57,3280.9 664.48,3255 715,3255 v1(716,3254) ; v1(648,3858) 646.49,3858 627,3877.49 627,4114 R63.1@732,4219
  Bottom Layer w8: v1(648,3858) 713,3793 713,3257 v1(716,3254)
PA12: CN5.28 R64.1 U18.73 | length 1726.9
  Top Layer w8: CN5.28@165,3061 165.26,3061.26 206.53,3061.26 255.63,3110.36 284.81,3110.36 311.54,3137.1 311.54,3171.54 442.87,3302.87 587.74,3302.87 U18.73@623.63,3266.99 ; U18.73@624.19,3266.42 659.61,3231 v1(692,3231) ; v1(649,3819) 607,3861 607,4153 R64.1@673,4219
  Bottom Layer w8: v1(649,3819) 692,3776 v1(692,3231)
PA13: CN5.25 R37.2 U18.76 | length 495.1
  Top Layer w8: CN5.25@265,2961 403.93,2961 U18.76@595.79,3152.85
  Bottom Layer w8: CN5.25@265,2961 347,2961 349,2963
PA14: CN5.24 R38.2 U18.77 | length 782.3
  Top Layer w8: CN5.24@165,2861 212,2908 378.77,2908 U18.77@609.7,3138.94
  Bottom Layer w8: CN5.24@165,2861 213,2909 304,2909 349,2864
PA15: CN5.23 U18.78 | length 468
  Top Layer w8: CN5.23@265,2861 359.61,2861 U18.78@623.63,3125.01
PB0: CN4.32 R73.2 U18.32 | length 644.9
  Top Layer w8: U18.32@1266.7,3322.66 1352.15,3408.11 1585.89,3408.11 1641.76,3352.24 1641.76,3324.72 1704,3262.48 CN4.32@1704,3261
  Bottom Layer w8: R73.2@1611.01,3264 1614.01,3261 CN4.32@1704,3261
PB1: CN4.33 R71.2 U18.33 | length 921.8
  Top Layer w8: U18.33@1235.63,3319.43 1340.6,3424.4 1599.6,3424.4 1659.06,3364.94 1659.06,3342.06 1689.45,3311.67 1753.69,3311.67 1803.01,3361 CN4.33@1804,3361
  Bottom Layer w8: R71.2@1611.01,3356 1652.44,3314.57 1754.95,3314.57 1801.39,3361 CN4.33@1804,3361
PB2: CN4.34 U18.34 | length 536.3
  Top Layer w8: U18.34@1238.86,3350.5 1330.05,3441.66 1614.55,3441.66 1695.2,3361 CN4.34@1704,3361
PB3: CN5.11 R70.2 U18.90 | length 1023.6
  Top Layer w8: CN5.11@265,2261 301.88,2261 484.85,2443.97 484.85,2652.17 U18.90@790.66,2957.98
  Bottom Layer w8: CN5.11@265,2261 341,2261 R70.2@349,2253
PB4: CN5.10 U18.91 | length 1097.3
  Top Layer w8: CN5.10@165,2161 172.4,2161 224.84,2213.44 301.59,2213.44 504.61,2416.46 504.61,2644.09 U18.91@804.58,2944.06
PB5: CN5.9 R46.2 U18.92 | length 1097.2
  Top Layer w8: CN5.9@265,2161 273.78,2169.78 298.95,2169.78 524.8,2395.63 524.8,2636.44 U18.92@818.5,2930.14
  Bottom Layer w8: CN5.9@265,2161 R46.2@349,2161
PB6: CN5.8 R53.2 U18.93 | length 1403.5
  Top Layer w8: CN5.8@165,2061 214.61,2110.61 285.88,2110.61 543.01,2367.74 543.01,2626.81 U18.93@832.42,2916.22
  Bottom Layer w8: CN5.8@165,2061 216,2010 292.59,2010 337,2054.41 337,2056 349,2068
PB7: CN5.7 R55.1 U18.94 | length 2271.1
  Top Layer w8: CN5.7@265,2061 278.82,2061 293.05,2075.23 293.49,2075.23 562.93,2344.67 562.93,2618.9 U18.94@846.34,2902.3 889,2944.97 889,3072 v1(763,3198)
  Bottom Layer w8: R55.1@524,3811 619,3811 661,3769 661,3219 682,3198 v1(763,3198)
PB9: CN5.5 U18.96 | length 1180.6
  Top Layer w8: CN5.5@265,1961 273.76,1969.76 298.96,1969.76 595.48,2266.28 595.48,2595.77 U18.96@874.17,2874.46
PB10: CN4.47 U18.47 | length 992.7
  Top Layer w8: U18.47@1057.9,3531.46 1198.49,3672.04 1402.83,3672.04 1648.48,3917.69 1648.48,3964.21 1701.27,4017 1760,4017 CN4.47@1804,4061
PB11: CN4.50 U18.50 | length 1002
  Top Layer w8: U18.50@1016.15,3573.21 1034.24,3591.31 1166.98,3724.04 1381.29,3724.04 1596.48,3939.23 1596.48,4059.84 1697.64,4161 CN4.50@1704,4161
PB12: CN5.50 U18.51 | length 1213.1
  Top Layer w8: CN5.50@165,4161 217.64,4213.64 284.1,4213.64 316.03,4181.71 316.03,4147.1 440.11,4023.02 440.11,3782.5 548.78,3673.84 829.23,3673.84 U18.51@929.85,3573.21
PB13: CN5.49 U18.52 | length 1032.6
  Top Layer w8: CN5.49@265,4161 424.11,4001.89 424.11,3775.87 542.15,3657.84 817.38,3657.84 U18.52@915.94,3559.3
PB14: CN5.48 U18.53 | length 1116.3
  Top Layer w8: CN5.48@165,4061 213.31,4109.31 282.59,4109.31 408.11,3983.78 408.11,3769.24 535.52,3641.84 805.55,3641.84 U18.53@902.01,3545.37
PB15: CN5.47 U18.54 | length 942.8
  Top Layer w8: CN5.47@265,4061 392.11,3933.89 392.11,3762.62 528.89,3625.84 793.71,3625.84 U18.54@888.1,3531.46
PC0: CN4.15 R87.1 U18.15 | length 2326.6
  Top Layer w8: v1(1140,3127) 1139.16,3126.16 1139.16,3085.52 U18.15@1211.02,3013.66 ; U18.15@1214.87,3009.81 1422.87,2801.81 1422.87,2676.82 1685.08,2414.61 1757.61,2414.61 CN4.15@1804,2461 ; R87.1@1314,4219 1314,4183 1271,4140 1271,3864 1325,3810 v1(1325,3773.94)
  Bottom Layer w8: v1@1140.23,3127.23 1140,3127.45 1140,3176.25 1381,3417.25 1381,3717.94 v1(1325,3773.94)
PC1: CN4.16 R88.1 U18.16 | length 2196.4
  Top Layer w8: v1(1172.51,3099) 1171.84,3098.33 1171.84,3080.39 U18.16@1224.64,3027.58 ; U18.16@1228.79,3023.73 1438.87,2813.65 1438.87,2683.44 1661.32,2461 CN4.16@1704,2461 ; R88.1@1255,4219 1255,3834 1288,3801 v1(1288,3797)
  Bottom Layer w8: v1@1173,3101 1170.71,3103.29 1170.71,3184.34 1408,3421.63 1408,3740 1350.06,3797.94 1288.94,3797.94 v1(1288,3797)
PC2: CN4.17 U18.17 | length 877.9
  Top Layer w8: U18.17@1242.71,3037.65 1454.87,2825.48 1454.87,2690.07 1632.07,2512.87 1755.87,2512.87 CN4.17@1804,2561
PC3: CN4.18 R85.1 U18.18 | length 829.2
  Top Layer w8: U18.18@1257.05,3051.15 1470.87,2837.33 1470.87,2696.7 1606.57,2561 CN4.18@1704,2561
  Bottom Layer w8: R85.1@1608,2563 1618,2563 1620,2561 CN4.18@1704,2561
PC4: CN4.30 U18.30 | length 579.1
  Top Layer w8: U18.30@1294.54,3294.83 1373.36,3373.64 1553.36,3373.64 1608,3319 1608,3235.55 1672.78,3170.77 1694.23,3170.77 CN4.30@1704,3161
PC5: CN4.31 U18.31 | length 689
  Top Layer w8: U18.31@1280.67,3308.75 1364.04,3392.11 1573.89,3392.11 1624,3342 1624,3277.95 1688.4,3213.55 1754.76,3213.55 1802.21,3261 CN4.31@1804,3261
PC6: CN5.36 U18.65 | length 645.4
  Top Layer w8: CN5.36@165,3461 169,3461 218.75,3510.75 389.01,3510.75 453.93,3445.83 666.55,3445.83 734.05,3378.34 U18.65@734.98,3378.34
PC7: CN5.35 U18.66 | length 496.1
  Top Layer w8: CN5.35@265,3461 267.59,3458.41 413.23,3458.41 442.46,3429.17 656.3,3429.17 U18.66@721.06,3364.42
PC8: CN5.34 U18.67 | length 589.7
  Top Layer w8: CN5.34@165,3361 169.43,3361 221.61,3413.17 644.46,3413.17 U18.67@707.14,3350.5
PC9: CN5.33 U18.68 | length 468.3
  Top Layer w8: CN5.33@265,3361 335.52,3361 371.7,3397.17 632.63,3397.17 U18.68@693.22,3336.58
PC10: CN5.22 U18.79 | length 617.6
  Top Layer w8: CN5.22@165,2761 213,2809 335.44,2809 U18.79@637.54,3111.1
PC11: CN5.21 U18.80 | length 525.7
  Top Layer w8: CN5.21@265,2761 265.53,2761.53 315.82,2761.53 U18.80@651.46,3097.17
PC12: CN5.20 U18.81 | length 675.3
  Top Layer w8: CN5.20@165,2661 218.38,2714.38 296.5,2714.38 U18.81@665.38,3083.26
PC13: CN4.7 U18.7 | length 2242.4
  Top Layer w8: U18.7@1100.3,2902.3 1100.3,2901.67 1183,2818.97 1183,2670.58 1026.42,2514 799.09,2514 777.83,2492.74 777.83,2134.15 943.85,1968.12 1647.02,1968.12 1685.95,2007.05 1759.6,2007.05 1804,2051.45 CN4.7@1804,2061
PD0: CN5.19 U18.82 | length 583.9
  Top Layer w8: CN5.19@265,2661 271.67,2661 660.86,3050.2 660.86,3050.89 U18.82@679.3,3069.34
PD1: CN5.18 U18.83 | length 761.4
  Top Layer w8: CN5.18@165,2561 165,2569 173,2569 216.27,2612.27 290.73,2612.27 316.1,2637.64 316.1,2678.18 U18.83@693.22,3055.3
PD2: CN5.17 R67.2 U18.84 | length 763.4
  Top Layer w9: CN5.17@265,2561 273.29,2569.29 299.56,2569.29 338.25,2607.99 338.25,2672.61 U18.84@707.14,3041.5
  Bottom Layer w8: CN5.17@265,2561 348,2561 R67.2@349,2562
PD3: CN5.16 U18.85 | length 840.9
  Top Layer w9: CN5.16@165,2461 174,2461 174,2470 213,2509 279.06,2509 366.77,2596.71 366.77,2673.29 U18.85@721.06,3027.58
PD4: CN5.15 U18.86 | length 759.2
  Top Layer w9: CN5.15@265,2461 274.58,2470.58 294.91,2470.58 390.99,2566.66 390.99,2669.67 U18.86@734.98,3013.66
